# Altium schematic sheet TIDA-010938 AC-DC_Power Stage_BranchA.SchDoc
size 558 x 431 mm; Date: Not shown in title block; ApprovedBy: Not shown in title block; CheckedBy: Not shown in title block; Author: Not shown in title block; CompanyName: Not shown in title block; Engineer: Not shown in title block; Organization: Not shown in title block; Address1: Not shown in title block; Address2: Not shown in title block; Address3: Not shown in title block; Address4: Not shown in title block; DocumentNumber: 2; Revision: Use project parameter SCH_Rev; SheetNumber: 3; SheetTotal: 11; PageSetup: Record=PageOptions¦CenterHorizontal=True¦CenterVertical=True¦PrintScale=1.00¦XCorrection=1.00¦YCorrection=1.00¦PrintKind=0¦BorderSize=5000000¦LeftOffset=0¦BottomOffset=0¦Orientation=2¦PaperLength=1000¦PaperWidth=1000¦Scale=100¦PaperSource=15¦PrintQuality=600¦MediaType=1¦DitherType=10¦PaperKind=Letter¦PrintScaleMode=1
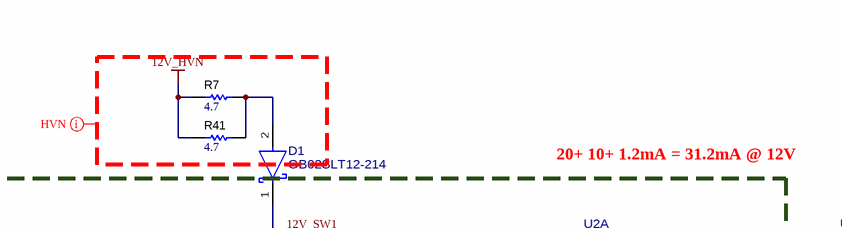
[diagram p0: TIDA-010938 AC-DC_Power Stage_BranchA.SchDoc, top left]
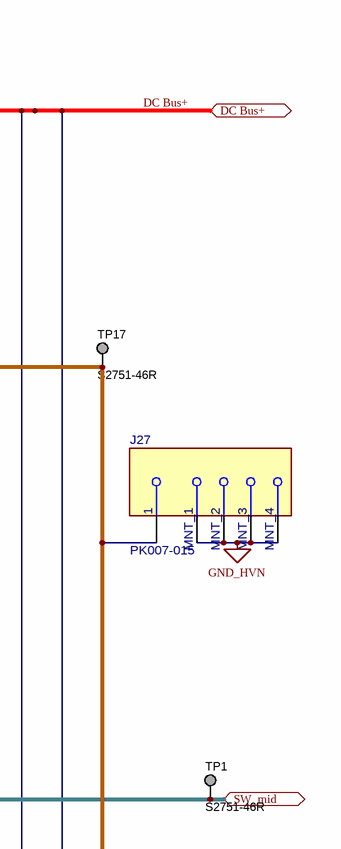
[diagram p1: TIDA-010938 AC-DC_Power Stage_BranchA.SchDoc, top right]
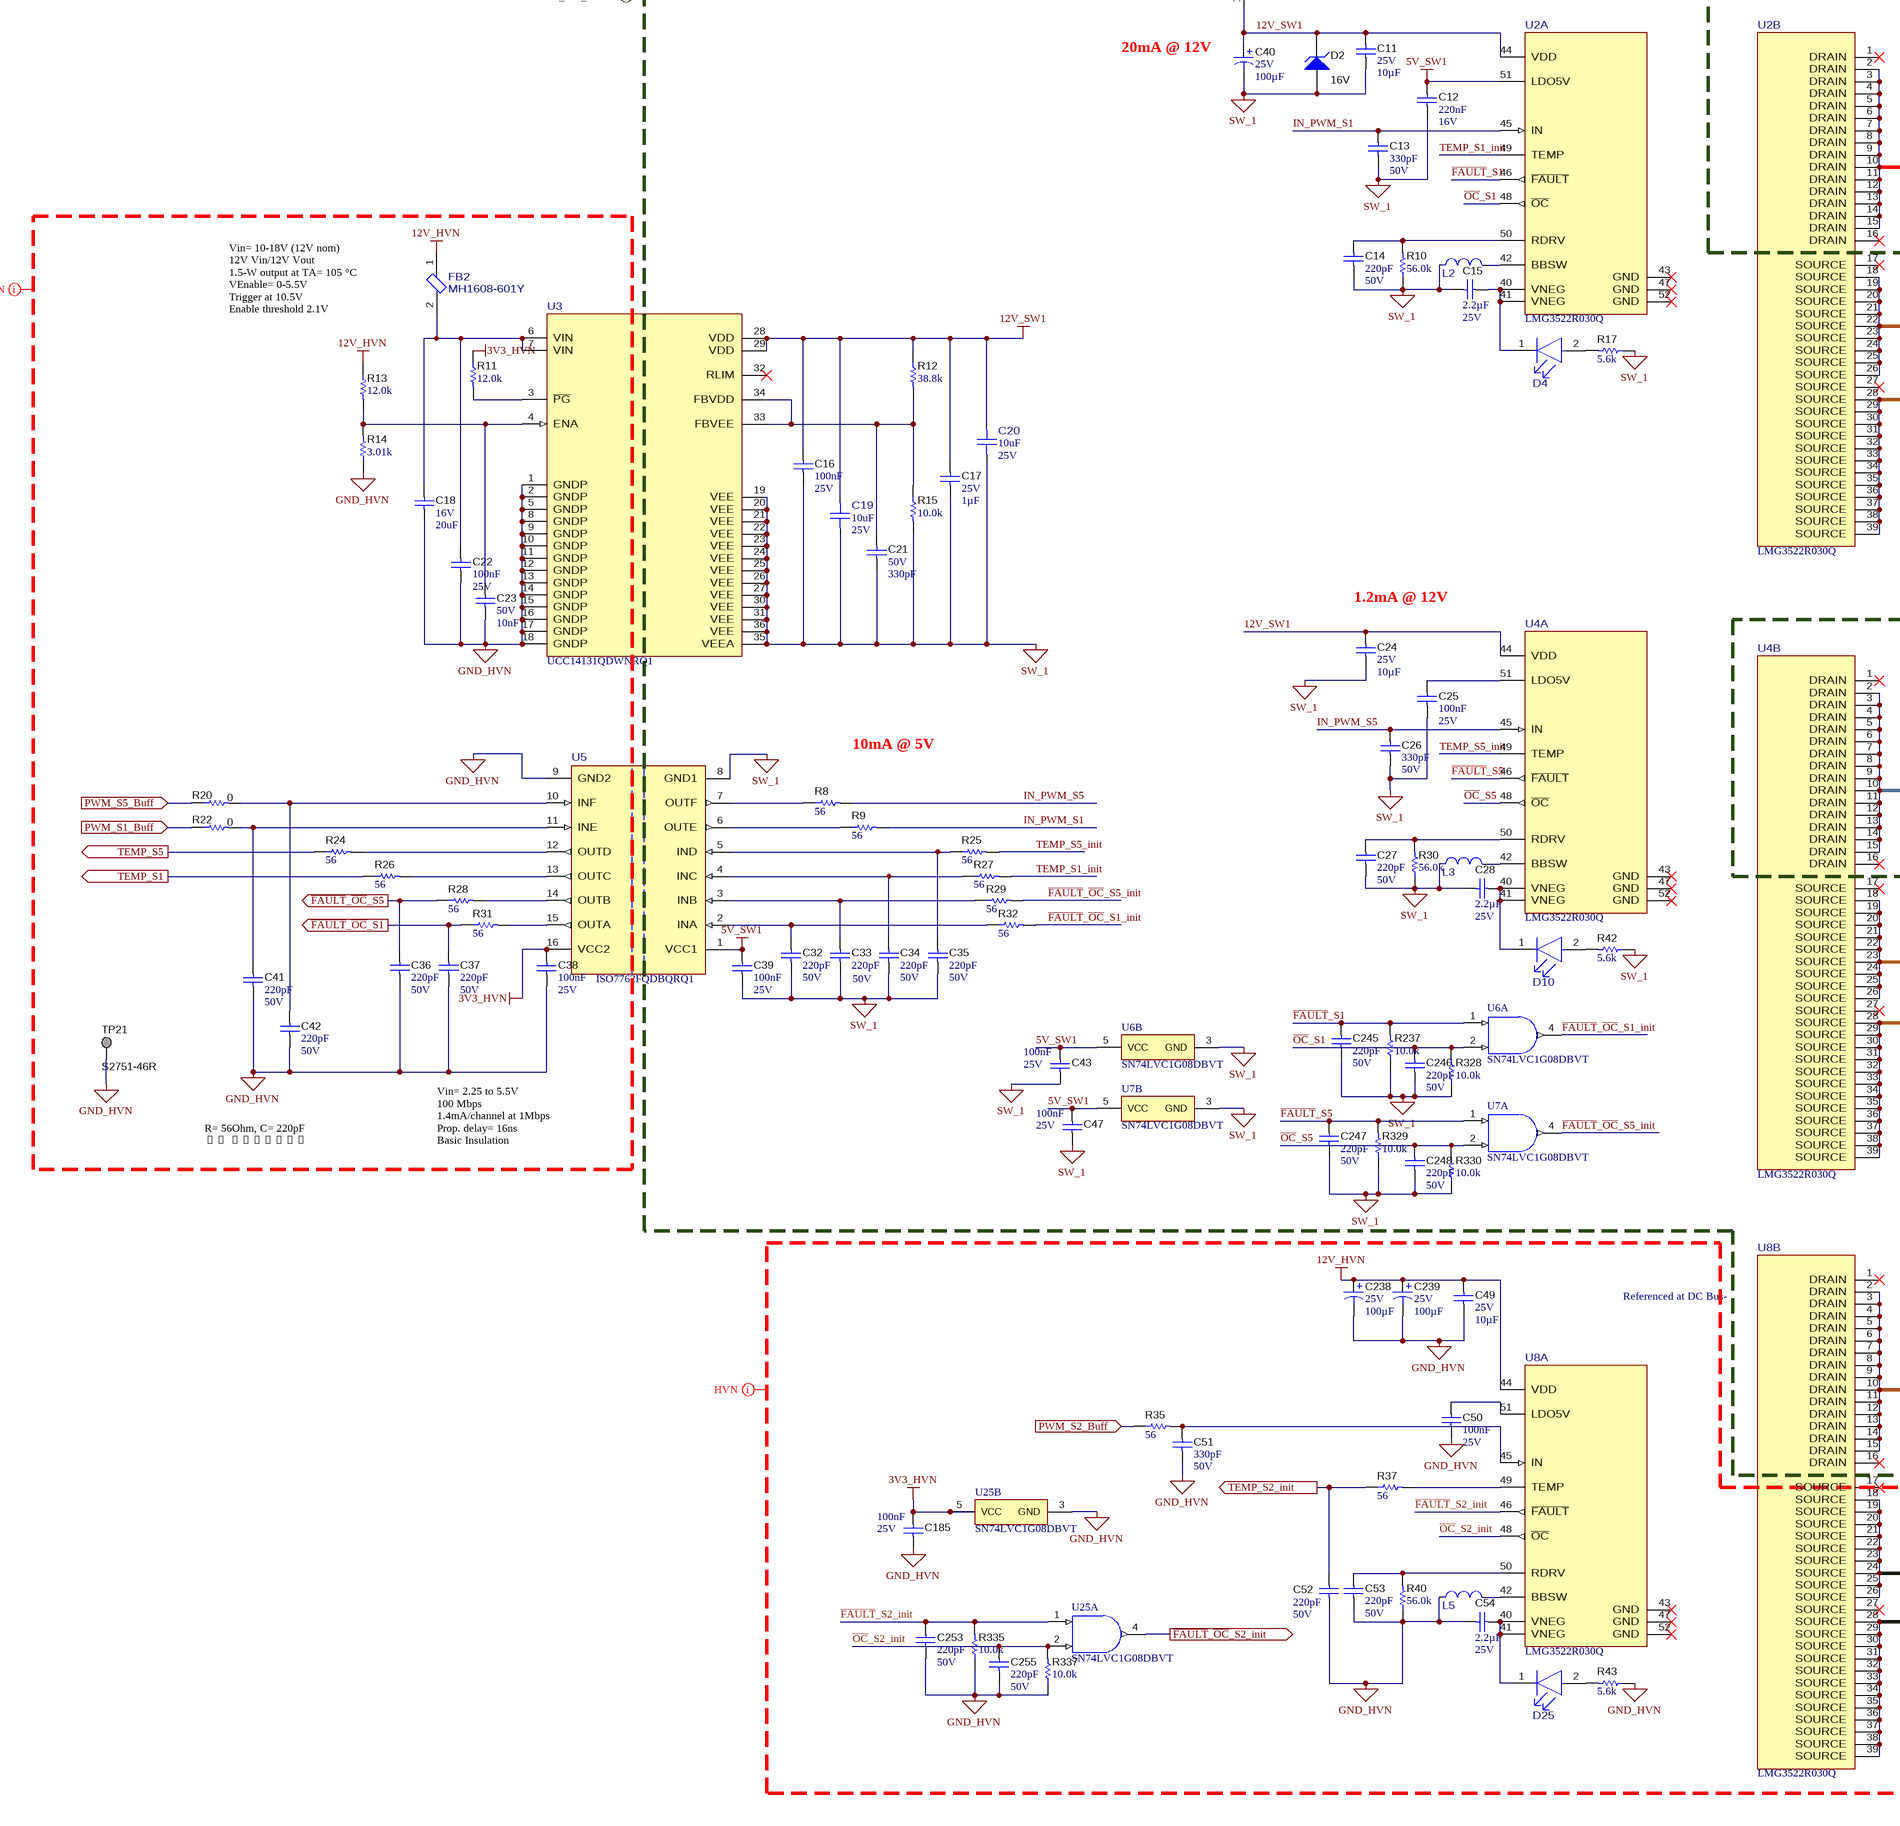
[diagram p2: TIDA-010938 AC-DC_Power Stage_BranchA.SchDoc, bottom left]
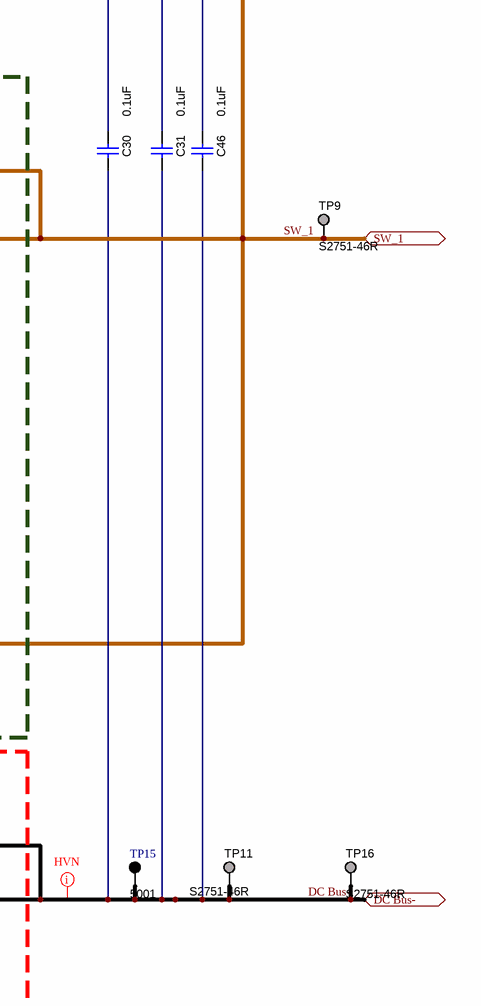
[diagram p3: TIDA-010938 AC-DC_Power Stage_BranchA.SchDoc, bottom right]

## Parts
C11  VDC_V: 25V  ValueDisplayed: 10µF  [1206_180]  (hidden comment: TMK316AB7106KLHT)
C12  Cap_F: 220nF  VDC_V: 16V  [0603]  (hidden comment: GRM188R71C224KA01D)
C13  Cap_F: 330pF  VDC_V: 50V  [0603]  (hidden comment: C0603C331K5RACTU)
C14  Cap_F: 220pF  VDC_V: 50V  [0603]  (hidden comment: GRM188R71H221KA01D)
C15  Cap_F: 2.2µF  VDC_V: 25V  [0805_HV]  (hidden comment: CGA4J3X7R1E225K125AB)
C16  Cap_F: 100nF  VDC_V: 25V  [0603]  (hidden comment: 06033C104JAT2A)
C17  VDC_V: 25V  ValueDisplayed: 1µF  [0603]  (hidden comment: TMK107BJ105KA-T)
C18  VDC_V: 16V  ValueDisplayed: 20uF  [0704]  (hidden comment: GRMJN7R61C206ME05)
C19  ValueDisplayed: 10uF  VDC_V: 25V  [FP-ZRB18AR61E106ME01L_0603-MFG]  (hidden comment: ZRB18AR61E106ME01L)
C20  ValueDisplayed: 10uF  VDC_V: 25V  [FP-ZRB18AR61E106ME01L_0603-MFG]  (hidden comment: ZRB18AR61E106ME01L)
C21  VDC_V: 50V  ValueDisplayed: 330pF  [0603]  (hidden comment: GRM1885C1H331JA01D)
C22  Cap_F: 100nF  VDC_V: 25V  [0603]  (hidden comment: 06033C104JAT2A)
C23  VDC_V: 50V  Cap_F: 10nF  [0603]  (hidden comment: 885012206089)
C24  VDC_V: 25V  ValueDisplayed: 10µF  [1206_180]  (hidden comment: TMK316AB7106KLHT)
C25  Cap_F: 100nF  VDC_V: 25V  [0603]  (hidden comment: 06033C104JAT2A)
C26  Cap_F: 330pF  VDC_V: 50V  [0603]  (hidden comment: C0603C331K5RACTU)
C27  Cap_F: 220pF  VDC_V: 50V  [0603]  (hidden comment: GRM188R71H221KA01D)
C28  Cap_F: 2.2µF  VDC_V: 25V  [0805_HV]  (hidden comment: CGA4J3X7R1E225K125AB)
C30  ValueDisplayed: 0.1uF  [1812_254]  (hidden comment: C1812W104KDRACTU)
C31  ValueDisplayed: 0.1uF  [1812_254]  (hidden comment: C1812W104KDRACTU)
C32  Cap_F: 220pF  VDC_V: 50V  [0603]  (hidden comment: GRM188R71H221KA01D)
C33  Cap_F: 220pF  VDC_V: 50V  [0603]  (hidden comment: GRM188R71H221KA01D)
C34  Cap_F: 220pF  VDC_V: 50V  [0603]  (hidden comment: GRM188R71H221KA01D)
C35  Cap_F: 220pF  VDC_V: 50V  [0603]  (hidden comment: GRM188R71H221KA01D)
C36  Cap_F: 220pF  VDC_V: 50V  [0603]  (hidden comment: GRM188R71H221KA01D)
C37  Cap_F: 220pF  VDC_V: 50V  [0603]  (hidden comment: GRM188R71H221KA01D)
C38  Cap_F: 100nF  VDC_V: 25V  [0603]  (hidden comment: 06033C104JAT2A)
C39  Cap_F: 100nF  VDC_V: 25V  [0603]  (hidden comment: 06033C104JAT2A)
C40  VDC_V: 25V  ValueDisplayed: 100µF  [UWT_630x770]  (hidden comment: UWT1E101MCL1GS)
C41  Cap_F: 220pF  VDC_V: 50V  [0603]  (hidden comment: GRM188R71H221KA01D)
C42  Cap_F: 220pF  VDC_V: 50V  [0603]  (hidden comment: GRM188R71H221KA01D)
C43  Cap_F: 100nF  VDC_V: 25V  [0603]  (hidden comment: 06033C104JAT2A)
C46  ValueDisplayed: 0.1uF  [1812_254]  (hidden comment: C1812W104KDRACTU)
C47  Cap_F: 100nF  VDC_V: 25V  [0603]  (hidden comment: 06033C104JAT2A)
C49  VDC_V: 25V  ValueDisplayed: 10µF  [1206_180]  (hidden comment: TMK316AB7106KLHT)
C50  Cap_F: 100nF  VDC_V: 25V  [0603]  (hidden comment: 06033C104JAT2A)
C51  Cap_F: 330pF  VDC_V: 50V  [0603]  (hidden comment: C0603C331K5RACTU)
C52  Cap_F: 220pF  VDC_V: 50V  [0603]  (hidden comment: GRM188R71H221KA01D)
C53  Cap_F: 220pF  VDC_V: 50V  [0603]  (hidden comment: GRM188R71H221KA01D)
C54  Cap_F: 2.2µF  VDC_V: 25V  [0805_HV]  (hidden comment: CGA4J3X7R1E225K125AB)
C185  Cap_F: 100nF  VDC_V: 25V  [0603]  (hidden comment: 06033C104JAT2A)
C238  VDC_V: 25V  ValueDisplayed: 100µF  [UWT_630x770]  (hidden comment: UWT1E101MCL1GS)
C239  VDC_V: 25V  ValueDisplayed: 100µF  [UWT_630x770]  (hidden comment: UWT1E101MCL1GS)
C245  Cap_F: 220pF  VDC_V: 50V  [0603]  (hidden comment: GRM188R71H221KA01D)
C246  Cap_F: 220pF  VDC_V: 50V  [0603]  (hidden comment: GRM188R71H221KA01D)
C247  Cap_F: 220pF  VDC_V: 50V  [0603]  (hidden comment: GRM188R71H221KA01D)
C248  Cap_F: 220pF  VDC_V: 50V  [0603]  (hidden comment: GRM188R71H221KA01D)
C253  Cap_F: 220pF  VDC_V: 50V  [0603]  (hidden comment: GRM188R71H221KA01D)
C255  Cap_F: 220pF  VDC_V: 50V  [0603]  (hidden comment: GRM188R71H221KA01D)
D1  GB02SLT12-214  [FP-GB02SLT12-214_DO-214AA-MFG]
D2  value 16V  [SOD-123]  (hidden comment: BZT52C16-7-F)
D4  KG DELLS1.22-JGKH-24  [FP-KG DELLS1.22-JGKH-24_0603-MFG]  (value not drawn)
D10  KG DELLS1.22-JGKH-24  [FP-KG DELLS1.22-JGKH-24_0603-MFG]  (value not drawn)
D25  KG DELLS1.22-JGKH-24  [FP-KG DELLS1.22-JGKH-24_0603-MFG]  (value not drawn)
FB2  MH1608-601Y  [FP-MH1608-601Y_0603-MFG]
J27  PK007-015  [FP-PK007-015_CONN_TESTCLIP-MFG]
L2  SDEM20161T-4R7MS  [FP-SDEM20161T-4R7MS_SMD2-MFG]  (value not drawn)
L3  SDEM20161T-4R7MS  [FP-SDEM20161T-4R7MS_SMD2-MFG]  (value not drawn)
L5  SDEM20161T-4R7MS  [FP-SDEM20161T-4R7MS_SMD2-MFG]  (value not drawn)
R7  ValueDisplayed: 4.7  [1206]  (hidden comment: CRCW12064R70JNEAHP)
R8  ValueDisplayed: 56  [0603]  (hidden comment: RG1608P-560-B-T5)
R9  ValueDisplayed: 56  [0603]  (hidden comment: RG1608P-560-B-T5)
R10  ValueDisplayed: 56.0k  [0603]  (hidden comment: RG1608P-563-B-T5)
R11  ValueDisplayed: 12.0k  [0603]  (hidden comment: ERJ-3EKF1202V)
R12  ValueDisplayed: 38.8k  [0603]  (hidden comment: RT0603DRE0738K8L)
R13  ValueDisplayed: 12.0k  [0603]  (hidden comment: ERJ-3EKF1202V)
R14  ValueDisplayed: 3.01k  [0603]  (hidden comment: RC0603FR-073K01L)
R15  ValueDisplayed: 10.0k  [0603]  (hidden comment: RG1608P-103-B-T5)
R17  ValueDisplayed: 5.6k  [0603]  (hidden comment: RC0603JR-075K6L)
R20  ValueDisplayed: 0  [0603]  (hidden comment: RCS06030000Z0EA)
R22  ValueDisplayed: 0  [0603]  (hidden comment: RCS06030000Z0EA)
R24  ValueDisplayed: 56  [0603]  (hidden comment: RG1608P-560-B-T5)
R25  ValueDisplayed: 56  [0603]  (hidden comment: RG1608P-560-B-T5)
R26  ValueDisplayed: 56  [0603]  (hidden comment: RG1608P-560-B-T5)
R27  ValueDisplayed: 56  [0603]  (hidden comment: RG1608P-560-B-T5)
R28  ValueDisplayed: 56  [0603]  (hidden comment: RG1608P-560-B-T5)
R29  ValueDisplayed: 56  [0603]  (hidden comment: RG1608P-560-B-T5)
R30  ValueDisplayed: 56.0k  [0603]  (hidden comment: RG1608P-563-B-T5)
R31  ValueDisplayed: 56  [0603]  (hidden comment: RG1608P-560-B-T5)
R32  ValueDisplayed: 56  [0603]  (hidden comment: RG1608P-560-B-T5)
R35  ValueDisplayed: 56  [0603]  (hidden comment: RG1608P-560-B-T5)
R37  ValueDisplayed: 56  [0603]  (hidden comment: RG1608P-560-B-T5)
R40  ValueDisplayed: 56.0k  [0603]  (hidden comment: RG1608P-563-B-T5)
R41  ValueDisplayed: 4.7  [1206]  (hidden comment: CRCW12064R70JNEAHP)
R42  ValueDisplayed: 5.6k  [0603]  (hidden comment: RC0603JR-075K6L)
R43  ValueDisplayed: 5.6k  [0603]  (hidden comment: RC0603JR-075K6L)
R237  ValueDisplayed: 10.0k  [0603]  (hidden comment: RG1608P-103-B-T5)
R328  ValueDisplayed: 10.0k  [0603]  (hidden comment: RG1608P-103-B-T5)
R329  ValueDisplayed: 10.0k  [0603]  (hidden comment: RG1608P-103-B-T5)
R330  ValueDisplayed: 10.0k  [0603]  (hidden comment: RG1608P-103-B-T5)
R335  ValueDisplayed: 10.0k  [0603]  (hidden comment: RG1608P-103-B-T5)
R337  ValueDisplayed: 10.0k  [0603]  (hidden comment: RG1608P-103-B-T5)
TP1  S2751-46R  [Harwin_S2751-46R]  (no BOM)
TP9  S2751-46R  [Harwin_S2751-46R]  (no BOM)
TP11  S2751-46R  [Harwin_S2751-46R]  (no BOM)
TP15  5001  [Keystone5001]
TP16  S2751-46R  [Harwin_S2751-46R]  (no BOM)
TP17  S2751-46R  [Harwin_S2751-46R]  (no BOM)
TP21  S2751-46R  [Harwin_S2751-46R]  (no BOM)
U2  LMG3522R030Q  [RQS0052C-C01-MFG]  (parts A,B of 2)
U3  UCC14131QDWNRQ1  [DWJ0036A-MFG]
U4  LMG3522R030Q  [RQS0052C-C01-MFG]  (parts A,B of 2)
U5  ISO7762FQDBQRQ1  [DBQ0016A-MFG]
U6  SN74LVC1G08DBVT  [DBV0005A_N]  (parts A,B of 2)
U7  SN74LVC1G08DBVT  [DBV0005A_N]  (parts A,B of 2)
U8  LMG3522R030Q  [RQS0052C-C01-MFG]  (parts A,B of 2)
U25  SN74LVC1G08DBVT  [DBV0005A_N]  (parts A,B of 2)

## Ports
DC Bus+ (bidir), DC Bus- (bidir), PWM_S1_Buff (in), PWM_S2_Buff (in), PWM_S5_Buff (in), SW_1 (bidir), SW_mid (bidir), TEMP_S1 (out), TEMP_S2_init (out), TEMP_S5 (out), ~{FAULT}_~{OC}_S1 (out), ~{FAULT}_~{OC}_S2_init (out), ~{FAULT}_~{OC}_S5 (out)

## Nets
3V3_HVN: C38.1 C185.1 R11.1 U5.16(VCC2) U25.5(VCC)
5V_SW1: C12.1 C39.1 C43.1 C47.1 U2.51(LDO5V) U5.1(VCC1) U6.5(VCC) U7.5(VCC)
12V_HVN: C49.1 C238.1(+) C239.1(+) FB2.1 R7.1 R13.1 R41.1 U8.44(VDD)
12V_SW1: C11.1 C16.2 C17.2 C19.2 C20.1 C24.1 C40.1(+) D1.1(CATHODE) D2.1(K) R12.1 U2.44(VDD) U3.28(VDD) U3.29(VDD) U4.44(VDD)
GND_HVN: C18.1 C22.2 C23.1 C36.1 C37.1 C38.2 C41.1 C42.1 C49.2 C50.1 C51.1 C52.1 C53.1 C54.2 C185.2 C238.2(-) C239.2(-) C253.1 C255.1 J27.2(MNT_1) J27.3(MNT_2) J27.4(MNT_3) J27.5(MNT_4) L5.1 R14.1 R40.1 R43.1 R335.1 R337.1 TP21.1 U3.1(GNDP) U3.2(GNDP) U3.5(GNDP) U3.8(GNDP) U3.9(GNDP) U3.10(GNDP) U3.11(GNDP) U3.12(GNDP) U3.13(GNDP) U3.14(GNDP) U3.15(GNDP) U3.16(GNDP) U3.17(GNDP) U3.18(GNDP) U5.9(GND2) U25.3(GND)
SW_1: C11.2 C12.2 C13.1 C14.1 C15.2 C16.1 C17.1 C19.1 C20.2 C21.2 C24.2 C25.1 C26.2 C27.1 C28.2 C32.1 C33.1 C34.1 C35.1 C39.2 C40.2(-) C43.2 C47.2 C245.1 C246.1 C247.1 C248.1 D2.2(A) J27.1 L2.1 L3.1 R10.1 R15.2 R17.1 R30.1 R42.1 R237.1 R328.1 R329.1 R330.1 TP9.1 TP17.1 U2.18(SOURCE) U2.19(SOURCE) U2.20(SOURCE) U2.21(SOURCE) U2.22(SOURCE) U2.23(SOURCE) U2.24(SOURCE) U2.25(SOURCE) U2.26(SOURCE) U2.28(SOURCE) U2.29(SOURCE) U2.30(SOURCE) U2.31(SOURCE) U2.32(SOURCE) U2.33(SOURCE) U2.34(SOURCE) U2.35(SOURCE) U2.36(SOURCE) U2.37(SOURCE) U2.38(SOURCE) U2.39(SOURCE) U3.19(VEE) U3.20(VEE) U3.21(VEE) U3.22(VEE) U3.23(VEE) U3.24(VEE) U3.25(VEE) U3.26(VEE) U3.27(VEE) U3.30(VEE) U3.31(VEE) U3.35(VEEA) U3.36(VEE) U4.18(SOURCE) U4.19(SOURCE) U4.20(SOURCE) U4.21(SOURCE) U4.22(SOURCE) U4.23(SOURCE) U4.24(SOURCE) U4.25(SOURCE) U4.26(SOURCE) U4.28(SOURCE) U4.29(SOURCE) U4.30(SOURCE) U4.31(SOURCE) U4.32(SOURCE) U4.33(SOURCE) U4.34(SOURCE) U4.35(SOURCE) U4.36(SOURCE) U4.37(SOURCE) U4.38(SOURCE) U4.39(SOURCE) U5.8(GND1) U6.3(GND) U7.3(GND) U8.2(DRAIN) U8.3(DRAIN) U8.4(DRAIN) U8.5(DRAIN) U8.6(DRAIN) U8.7(DRAIN) U8.8(DRAIN) U8.9(DRAIN) U8.10(DRAIN) U8.11(DRAIN) U8.12(DRAIN) U8.13(DRAIN) U8.14(DRAIN) U8.15(DRAIN) ; port SW_1
DC Bus+: C30.1 C31.1 C46.1 U2.2(DRAIN) U2.3(DRAIN) U2.4(DRAIN) U2.5(DRAIN) U2.6(DRAIN) U2.7(DRAIN) U2.8(DRAIN) U2.9(DRAIN) U2.10(DRAIN) U2.11(DRAIN) U2.12(DRAIN) U2.13(DRAIN) U2.14(DRAIN) U2.15(DRAIN) ; port DC Bus+
DC Bus-: C30.2 C31.2 C46.2 TP11.1 TP15.1 TP16.1 U8.18(SOURCE) U8.19(SOURCE) U8.20(SOURCE) U8.21(SOURCE) U8.22(SOURCE) U8.23(SOURCE) U8.24(SOURCE) U8.25(SOURCE) U8.26(SOURCE) U8.28(SOURCE) U8.29(SOURCE) U8.30(SOURCE) U8.31(SOURCE) U8.32(SOURCE) U8.33(SOURCE) U8.34(SOURCE) U8.35(SOURCE) U8.36(SOURCE) U8.37(SOURCE) U8.38(SOURCE) U8.39(SOURCE) ; port DC Bus-
~{FAULT}_~{OC}_S1: C37.2 R31.1 ; port ~{FAULT}_~{OC}_S1
~{FAULT}_~{OC}_S1_init: R32.2 U6.4(Y)
~{FAULT}_~{OC}_S2_init: U25.4(Y) ; port ~{FAULT}_~{OC}_S2_init
~{FAULT}_~{OC}_S5: C36.2 R28.1 ; port ~{FAULT}_~{OC}_S5
~{FAULT}_~{OC}_S5_init: R29.2 U7.4(Y)
~{FAULT}_S1: C245.2 R237.2 U2.46(~{FAULT}) U6.1(A)
~{FAULT}_S2_init: C253.2 R335.2 U8.46(~{FAULT}) U25.1(A)
~{FAULT}_S5: C247.2 R329.2 U4.46(~{FAULT}) U7.1(A)
IN_PWM_S1: C13.2 R9.2 U2.45(IN)
IN_PWM_S5: C26.1 R8.2 U4.45(IN)
~{OC}_S1: C246.2 R328.2 U2.48(~{OC}) U6.2(B)
~{OC}_S2_init: C255.2 R337.2 U8.48(~{OC}) U25.2(B)
~{OC}_S5: C248.2 R330.2 U4.48(~{OC}) U7.2(B)
PWM_S1_Buff: R22.1 ; port PWM_S1_Buff
PWM_S2_Buff: R35.1 ; port PWM_S2_Buff
PWM_S5_Buff: R20.1 ; port PWM_S5_Buff
SW_mid: TP1.1 U4.2(DRAIN) U4.3(DRAIN) U4.4(DRAIN) U4.5(DRAIN) U4.6(DRAIN) U4.7(DRAIN) U4.8(DRAIN) U4.9(DRAIN) U4.10(DRAIN) U4.11(DRAIN) U4.12(DRAIN) U4.13(DRAIN) U4.14(DRAIN) U4.15(DRAIN) ; port SW_mid
TEMP_S1: R26.1 ; port TEMP_S1
TEMP_S1_init: R27.2 U2.49(TEMP)
TEMP_S2_init: C52.2 R37.1 ; port TEMP_S2_init
TEMP_S5: R24.1 ; port TEMP_S5
TEMP_S5_init: R25.2 U4.49(TEMP)
NetC14_2: C14.2 R10.2 U2.50(RDRV)
NetC15_1: C15.1 D4.1(CATHODE) U2.40(VNEG) U2.41(VNEG)
NetC18_2: C18.2 C22.1 FB2.2 U3.6(VIN) U3.7(VIN)
NetC21_1: C21.1 R12.2 R15.1 U3.33(FBVEE) U3.34(FBVDD)
NetC23_2: C23.2 R13.2 R14.2 U3.4(ENA)
NetC25_2: C25.2 U4.51(LDO5V)
NetC27_2: C27.2 R30.2 U4.50(RDRV)
NetC28_1: C28.1 D10.1(CATHODE) U4.40(VNEG) U4.41(VNEG)
NetC32_2: C32.2 R32.1 U5.2(INA)
NetC33_2: C33.2 R29.1 U5.3(INB)
NetC34_2: C34.2 R27.1 U5.4(INC)
NetC35_2: C35.2 R25.1 U5.5(IND)
NetC41_2: C41.2 R22.2 U5.11(INE)
NetC42_2: C42.2 R20.2 U5.10(INF)
NetC50_2: C50.2 U8.51(LDO5V)
NetC51_2: C51.2 R35.2 U8.45(IN)
NetC53_2: C53.2 R40.2 U8.50(RDRV)
NetC54_1: C54.1 D25.1(CATHODE) U8.40(VNEG) U8.41(VNEG)
NetD1_2: D1.2(ANODE) R7.2 R41.2
NetD4_2: D4.2(ANODE) R17.2
NetD10_2: D10.2(ANODE) R42.2
NetD25_2: D25.2(ANODE) R43.2
NetL2_2: L2.2 U2.42(BBSW)
NetL3_2: L3.2 U4.42(BBSW)
NetL5_2: L5.2 U8.42(BBSW)
NetR8_1: R8.1 U5.7(OUTF)
NetR9_1: R9.1 U5.6(OUTE)
NetR11_2: R11.2 U3.3(~{PG})
NetR24_2: R24.2 U5.12(OUTD)
NetR26_2: R26.2 U5.13(OUTC)
NetR28_2: R28.2 U5.14(OUTB)
NetR31_2: R31.2 U5.15(OUTA)
NetR37_2: R37.2 U8.49(TEMP)

Not connected (* = marked no-connect by the designer): U2 1(DRAIN)* 16(DRAIN)* 17(SOURCE)* 27(SOURCE)* 43(GND)* 47(GND)* 52(GND)*; U3 32(RLIM)*; U4 1(DRAIN)* 16(DRAIN)* 17(SOURCE)* 27(SOURCE)* 43(GND)* 47(GND)* 52(GND)*; U8 1(DRAIN)* 16(DRAIN)* 17(SOURCE)* 27(SOURCE)* 43(GND)* 47(GND)* 52(GND)*

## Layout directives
net class HV_SW_Node1: 5V_SW1, 12V_HVN, 12V_SW1, GND_HVN, IN_PWM_S1, IN_PWM_S5, SW_1, TEMP_S1_init, TEMP_S5_init, ~{FAULT}_S1, ~{FAULT}_S5, ~{FAULT}_~{OC}_S1_init, ~{FAULT}_~{OC}_S5_init, ~{OC}_S1, ~{OC}_S5
net class HVN: 3V3_HVN, 12V_HVN, DC Bus-, GND_HVN, ~{FAULT}_S2_init, ~{OC}_S2_init
net class HVP: DC Bus+
net class HV_SW_Mid: SW_mid

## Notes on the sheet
- 20+ 10+ 1.2mA = 31.2mA @ 12V
- (near C40) 20mA @ 12V
- Vin= 10-18V (12V nom)
  12V Vin/12V Vout
  1.5-W output at TA= 105 °C
  VEnable= 0-5.5V
  Trigger at 10.5V
  Enable threshold 2.1V
- (near C24) 1.2mA @ 12V
- 10mA @ 5V
- R= 56Ohm, C= 220pF
  𝜏= 1.23e-8
- Vin= 2.25 to 5.5V
  100 Mbps
  1.4mA/channel at 1Mbps
  Prop. delay= 16ns
  Basic Insulation
- Referenced at DC Bus-

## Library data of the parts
C11 C24 C49 = CMP-0750154-1: CAP, CERM, 10 µF, 25 V,+/- 10%, X7R, AEC-Q200 Grade 1, 1206; Manufacturer: Taiyo Yuden; AEC Qualified: Y; SizeZ_mm: 1.8; TaMax_C: 125°C; TaMin_C: -55°C; Cap_Case: 1206; Polarized: N; AEC Grade: 1; SizeY_mm: 1.6; Value: 10uF; SizeX_mm: 3.2; SizeAreaWB_mm2: 10.92; AEC Category: Q200; U/M: EA; SizeArea_mm2: 5.12
C12 = CMP-0007389-4: CAP, CERM, 0.22 uF, 16 V, +/- 10%, X7R, 0603; Manufacturer: MuRata; TaMin_C: -55°C; Polarized: N; SizeAreaWB_mm2: 4.68; Value1: Unknown; U/M: EA; Value: 0.22uF; TaMax_C: 125°C; SizeZ_mm: 1; SizeX_mm: 1.6; SizeY_mm: 0.8; SizeArea_mm2: 1.28; AEC Category: Q200
C13 C26 C51 = CMP-0006921-4: CAP, CERM, 330 pF, 50 V, +/- 10%, X7R, 0603; Manufacturer: Kemet; TaMin_C: -55°C; Polarized: N; SizeAreaWB_mm2: 4.68; Value1: Unknown; U/M: EA; Value: 330pF; TaMax_C: 125°C; SizeZ_mm: 1; SizeX_mm: 1.6; SizeY_mm: 0.8; SizeArea_mm2: 1.28; AEC Category: Q200
C14 C27 C32-C37 C41 C42 C52 C53 C245-C248 C253 C255 = CMP-0007442-5: CAP, CERM, 220 pF, 50 V, +/- 10%, X7R, 0603; Manufacturer: MuRata; TaMin_C: -55°C; Polarized: N; SizeAreaWB_mm2: 4.68; Value1: Unknown; U/M: EA; Value: 220pF; TaMax_C: 125°C; SizeZ_mm: 1; SizeX_mm: 1.6; SizeY_mm: 0.8; SizeArea_mm2: 1.28; AEC Category: Q200
C15 C28 C54 = CMP-0007975-2: CAP, CERM, 2.2 uF, 25 V, +/- 10%, X7R, AEC-Q200 Grade 1, 0805; Manufacturer: TDK; TaMin_C: -55°C; Polarized: N; SizeAreaWB_mm2: 6.75; Value1: Unknown; U/M: EA; Value: 2.2uF; TaMax_C: 125°C; SizeZ_mm: 1.45; SizeX_mm: 2; SizeY_mm: 1.25; Cap_Case: 0805; SizeArea_mm2: 2.5; AEC Qualified: Y; AEC Grade: 1; AEC Category: Q200
C16 C22 C25 C38 C39 C43 C47 C50 C185 = CMP-0006752-5: CAP, CERM, 0.1 uF, 25 V, +/- 5%, X7R, 0603; Manufacturer: AVX; TaMin_C: -55°C; ESR_ohm: 0.05; Polarized: N; SizeAreaWB_mm2: 4.68; Value1: 0.05 ohm; U/M: EA; Value: 0.1uF; TaMax_C: 125°C; SizeZ_mm: 1; SizeX_mm: 1.6; SizeY_mm: 0.8; SizeArea_mm2: 1.28; AEC Category: Q200
C17 = CMP-0086152-1: CAP, CERM, 1 µF, 25 V,+/- 10%, X5R, 0603; Manufacturer: Taiyo Yuden; SizeAreaWB_mm2: 4.68; SizeZ_mm: 1; U/M: EA; Green_REACh: Passed; Value: 1uF; AEC Qualified: N; TaMax_C: 85°C; Green_Lifecycle: Active; AEC Category: Q200; SizeArea_mm2: 1.28; TaMin_C: -55°C; SizeY_mm: 0.8; SizeX_mm: 1.6
C18 = CMP-0009474-2: CAP, CERM, 20 uF, 16 V, +/- 20%, X5R, 0704; Manufacturer: MuRata; TaMin_C: -55°C; Polarized: N; SizeAreaWB_mm2: 5.6; Value1: Unknown; U/M: EA; Value: 20uF; TaMax_C: 85°C; SizeZ_mm: 0.8; SizeX_mm: 1; SizeY_mm: 1.8; Cap_F: 20µF; AEC Category: Q200
C19 C20 = CMP-0094458-1: 10µF ±20% 25V Ceramic Capacitor X5R 0603 (1608 Metric); Manufacturer: Murata Electronics; SizeZ_mm: 1.2mm; AEC Qualified: No
C21 = CMP-0007209-4: CAP, CERM, 330 pF, 50 V, +/- 5%, C0G/NP0, 0603; Manufacturer: MuRata; TaMin_C: -55°C; Polarized: N; SizeAreaWB_mm2: 4.68; Value1: Unknown; U/M: EA; Value: 330pF; TaMax_C: 125°C; SizeZ_mm: 1; SizeX_mm: 1.6; SizeY_mm: 0.8; SizeArea_mm2: 1.28; AEC Category: Q200
C23 = CMP-0750039-1: CAP, CERM, 0.01 µF, 50 V,+/- 10%, X7R, 0603; Manufacturer: Wurth Elektronik; Polarized: N; AEC Category: Q200; TaMax_C: 125°C; SizeAreaWB_mm2: 4.68; Value: 0.01uF; SizeArea_mm2: 1.28; SizeY_mm: 0.8; SizeZ_mm: 1; ValueDisplayed: 0.01µF; SizeX_mm: 1.6; U/M: EA; TaMin_C: -55°C
C30 C31 C46 = CMP-0009326-2: CAP, CERM, 0.1 uF, 1000 V, +/- 10%, X7R, 1812; Manufacturer: Kemet; Polarized: N; Value: 0.1uF; U/M: EA; Cap_F: 100nF; Value1: Unknown; VDC_V: 1kV; Value2: 1000V; TaMin_C: -55°C; TaMax_C: 125°C; Cap_Case: 1812; AEC Category: Q200; SizeArea_mm2: 14.4; SizeAreaWB_mm2: 23.1; SizeX_mm: 4.5; SizeY_mm: 3.2; SizeZ_mm: 2.54
C40 C238 C239 = CMP-0081462-1: CAP, AL, 100 µF, 25 V, +/- 20%, SMD; Manufacturer: Nichicon; TaMin_C: -55°C; Polarized: Y; SizeAreaWB_mm2: 77.4; U/M: EA; Value: 100uF; TaMax_C: 105°C; SizeZ_mm: 8; SizeX_mm: 7; SizeY_mm: 6.6; Cap_Case: 6.3x7.7mm; SizeArea_mm2: 46.2; CompType: Capacitor; AEC Qualified: N; IRMS_A: 91mA; AEC Category: Q200
D1 = CMP-0095009-1: Diode Silicon Carbide Schottky 1200 V 2A (DC) Surface Mount DO-214AA; Manufacturer: GeneSiC Semiconductor; Max Surge Forward Current: 20A; ValueDisplayed: 122pF; Vf_V: 1.2kV; Peak Reverse Current: 1uA; SizeZ_mm: 2.44mm; AEC Qualified: No; TJmax_C: 175°C
D2 = CMP-0005769-4: Diode, Zener, 16 V, 500 mW, AEC-Q101, SOD-123; Manufacturer: Diodes Inc.; SizeZ_mm: 1.35; AEC Qualified: Y; SizeX_mm: 3.85; AEC Category: Q101; Power_W: 500mW; SizeY_mm: 1.7; Value1: 0.5W; SizeAreaWB_mm2: 13.095; SizeArea_mm2: 6.545; RJA_CperW: 338
D4 D10 D25 = CMP-0093310-1: Standard LEDs - SMD Green TOPLED E 1608; Manufacturer: Osram Opto; AEC Grade: Grade 2; LambdaP: 572nm; SizeZ_mm: 0.7mm; LuminousFlux_PhiV: 0.016-0.0295lm; Luminous Intensity: 4.5-9.7mcd; LambdaD: 570nm; Tjmax_C: 125°C; Angle: 120°; Led Orientation: Top View; Forward Current: 2mA; Vf_V: 1.8V; AEC Qualified: Yes; Vr_V: 12V
FB2 = CMP-0037505-1: 600 Ohms @ 100 MHz 1 Power, Signal Line Ferrite Bead 0603 (1608 Metric) 1A 200mOhm; Manufacturer: Bourns; DCR_ohm: 0.2; SizeZ_mm: 1mm; AEC Qualified: No; Impedance At Frequency: 600Ω @ 100MHz; Test Frequency: 100MHz; Tolerance_%: 25%
J27 = CMP-0089221-2: Test Clip, Lead, Probe Adapter for use with LeCroy Passive Probes; Manufacturer: Teledyne Lecroy; AEC Qualified: No; Is Female: yes; Conn Orientation: Vertical
L2 L3 L5 = CMP-0089347-1: 4.7µH Unshielded Inductor 1.1A 426mOhm Max 0806 (2016 Metric); Manufacturer: Cyntec; AEC Qualified: No; Material: Metal Dust; Isat: 1.26A; Test Frequency: 1MHz; DCR_ohm: 0.426; SizeZ_mm: 1mm; Tolerance_%: 20%
R7 R41 = CMP-0018694-3: RES, 4.7, 5%, 0.75 W, AEC-Q200 Grade 0, 1206; Manufacturer: Vishay-Dale; Power_W: 750mW; TempCo: 200 ppm/C; Value_Code: 4R70; Value: 4.7; EIA_Code: E24; SizeX_mm: 3.2; SizeY_mm: 1.6; SizeZ_mm: 1.35; Value2: 0.75W; SizeArea_mm2: 5.12; AEC Qualified: Y; AEC Grade: 0; AEC Category: Q200
R8 R9 R24-R29 R31 R32 R35 R37 = CMP-0023572-3: RES, 56, 0.1%, 0.1 W, 0603; Manufacturer: Susumu Co Ltd; Power_W: 100mW; TempCo: 25 ppm/C; Value_Code: 56R0; U/M: EA; Value: 56; SizeX_mm: 1.6; SizeY_mm: 0.8; SizeZ_mm: 1; Value2: 0.1W; SizeArea_mm2: 1.28; VDC_V: 75V; AEC Category: Q200
R10 R30 R40 = CMP-0023577-3: RES, 56.0 k, 0.1%, 0.1 W, 0603; Manufacturer: Susumu Co Ltd; Power_W: 100mW; TempCo: 25 ppm/C; Value_Code: 56k0; U/M: EA; Value: 56.0k; Res_ohm: 56k; SizeX_mm: 1.6; SizeY_mm: 0.8; SizeZ_mm: 1; Value2: 0.1W; SizeArea_mm2: 1.28; VDC_V: 75V; AEC Category: Q200
R11 R13 = CMP-0022685-3: RES, 12.0 k, 1%, 0.1 W, 0603; Manufacturer: Panasonic; Power_W: 100mW; TempCo: 100 ppm/C; Value_Code: 12k0; U/M: EA; Value: 12.0k; Res_ohm: 12k; SizeX_mm: 1.6; SizeY_mm: 0.8; SizeZ_mm: 1; Value2: 0.1W; SizeArea_mm2: 1.28; VDC_V: 75V; AEC Category: Q200
R12 = CMP-0025200-2: RES, 38.8 k, 0.5%, 0.1 W, 0603; Manufacturer: Yageo America; Power_W: 100mW; TempCo: 50 ppm/C; Value_Code: 38k8; U/M: EA; Value: 38.8k; EIA_Code: E192; SizeX_mm: 1.6; SizeY_mm: 0.8; SizeZ_mm: 1; Value2: 0.1W; SizeArea_mm2: 1.28; VDC_V: 75V; AEC Category: Q200
R14 = CMP-0023076-5: RES, 3.01 k, 1%, 0.1 W, 0603; Manufacturer: Yageo; Power_W: 100mW; TempCo: 100 ppm/C; Value_Code: 3k01; Value: 3.01k; EIA_Code: E96; SizeX_mm: 1.6; SizeY_mm: 0.8; SizeZ_mm: 1; Value2: 0.1W; SizeArea_mm2: 1.28; AEC Qualified: N; VDC_V: 75V; AEC Category: Q200; SizeAreaWB_mm2: 4.68
R15 = CMP-0023404-1: RES, 10.0 k, 0.1%, 0.1 W, 0603; Manufacturer: Susumu Co Ltd; Power_W: 100mW; TempCo: 25 ppm/C; Value_Code: 10k0; U/M: EA; Value: 10.0k; EIA_Code: E192; Res_ohm: 10k; SizeX_mm: 1.6; SizeY_mm: 0.8; SizeZ_mm: 1; Value2: 0.1W; SizeArea_mm2: 1.28; VDC_V: 75V; AEC Category: Q200
R17 R42 R43 = CMP-0025933-5: RES, 5.6 k, 5%, 0.1 W, 0603; Manufacturer: Yageo; Power_W: 100mW; TempCo: 100 ppm/C; Value_Code: 5k60; Value: 5.6k; EIA_Code: E24; SizeX_mm: 1.6; SizeY_mm: 0.8; SizeZ_mm: 1; Value2: 0.1W; SizeArea_mm2: 1.28; AEC Qualified: N; VDC_V: 75V; AEC Category: Q200; SizeAreaWB_mm2: 4.68
R20 R22 = CMP-0081973-1: RES, 0, 0%, 0.25 W, AEC-Q200 Grade 0, 0603; Manufacturer: Vishay-Dale; SizeAreaWB_mm2: 4.68; SizeArea_mm2: 1.28; AEC Qualified: Y; AEC Category: Q200; Value: 0; SizeZ_mm: 1; SizeY_mm: 0.8; Power_W: 250mW; Value2: 0.25W; SizeX_mm: 1.6
R237 R328-R330 R335 R337 = CMP-0023404-3: RES, 10.0 k, 0.1%, 0.1 W, 0603; Manufacturer: Susumu Co Ltd; Power_W: 100mW; TempCo: 25 ppm/C; Value_Code: 10k0; U/M: EA; Value: 10.0k; EIA_Code: E192; Res_ohm: 10k; SizeX_mm: 1.6; SizeY_mm: 0.8; SizeZ_mm: 1; Value2: 0.1W; SizeArea_mm2: 1.28; VDC_V: 75V; AEC Category: Q200
TP1 TP9 TP11 TP16 TP17 TP21 = CMP-0003968-1: Test Point, SMT; Manufacturer: Harwin
TP15 = CMP-0055138-2: Test Point, Miniature, Black, TH; Manufacturer: Keystone Electronics; ContactFinish: Silver; CNHeader: FALSE; Green_Lifecycle: Active; Green_REACh: Passed; CT: TRUE
U2 U4 U8 = CMP-0089967-3: 650-V 30-mΩ GaN FET with Integrated Driver and Protection; Manufacturer: Texas Instruments; Standoff Height: 0mm; TJmax_C: +125°C; AEC Qualified: Yes; Nominal Supply Current: 16mA; Min Supply Voltage: 7.5V; SizeZ_mm: 1mm; AEC Category: Q200; Output Voltage: 520V; CompType: IC; Number Of Outputs: 1; Max Supply Voltage: 18V; AEC Grade: Grade 1
U3 = CMP-0033793-2: Automotive 1.5-W, 12-V VIN / 12-VOUT, 15-V VIN / 15-V VOUT, HighDensity, > 5-kVRMS, Isolated DC/DC Module; Manufacturer: Texas Instruments; SizeZ_mm: 3.55mm; AEC Qualified: Yes; AEC Grade: Grade 1; Max Supply Voltage: 18V; Min Supply Voltage: 9V; Nominal Supply Current: 200-270mA; Number Of Outputs: 2; Output Type: AdjustableProgrammable; Output Voltage: 10-18V; Standoff Height: 0.1mm; Switching Frequency: 18MHz; TaMax_C: +125°C; TaMin_C: -40°C; TJmax_C: +150°C; AEC Category: Q200; CompType: IC
U5 = CMP-0091060-1: Automotive, robust EMC, six-channel, 4/2, reinforced digital isolator 16-SSOP -40 to 125; Manufacturer: Texas Instruments; AEC Qualified: Yes; AEC Grade: Grade 1; Standoff Height: 0.11mm; Min Supply Voltage: 2.25V; SizeZ_mm: 1.75mm; TaMax_C: +125°C; Nominal Supply Current: 2.1-25.7mA; TJmax_C: +150°C; Max Supply Voltage: 5.5V; TaMin_C: -40°C
U6 U7 U25 = CMP-0051571-2: Single 2-Input Positive-AND Gate, DBV0005A, SMALL T&R; Manufacturer: Texas Instruments; Voltage(Nom)(V): 1.8,2.5,3.3,5; Bits(#): 1; Rating: Catalog; F @ Nom Voltage(Max)(Mhz): 150; 3-State Output: No; Gate Type: AND; Output Drive (IOL/IOH)(Max)(mA): 32/-32; Technology Family: LVC; Logic: True; VCC(Max)(V): 5.5; ICC @ Nom Voltage(Max)(mA): 0.01; VCC(Min)(V): 1.65; tpd @ Nom Voltage(Max)(ns): 4.5,6,4,5; Input Type: CMOS/TTL; Output Type: CMOS; AEC Category: Q200; AEC Qualified: N; CompType: IC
